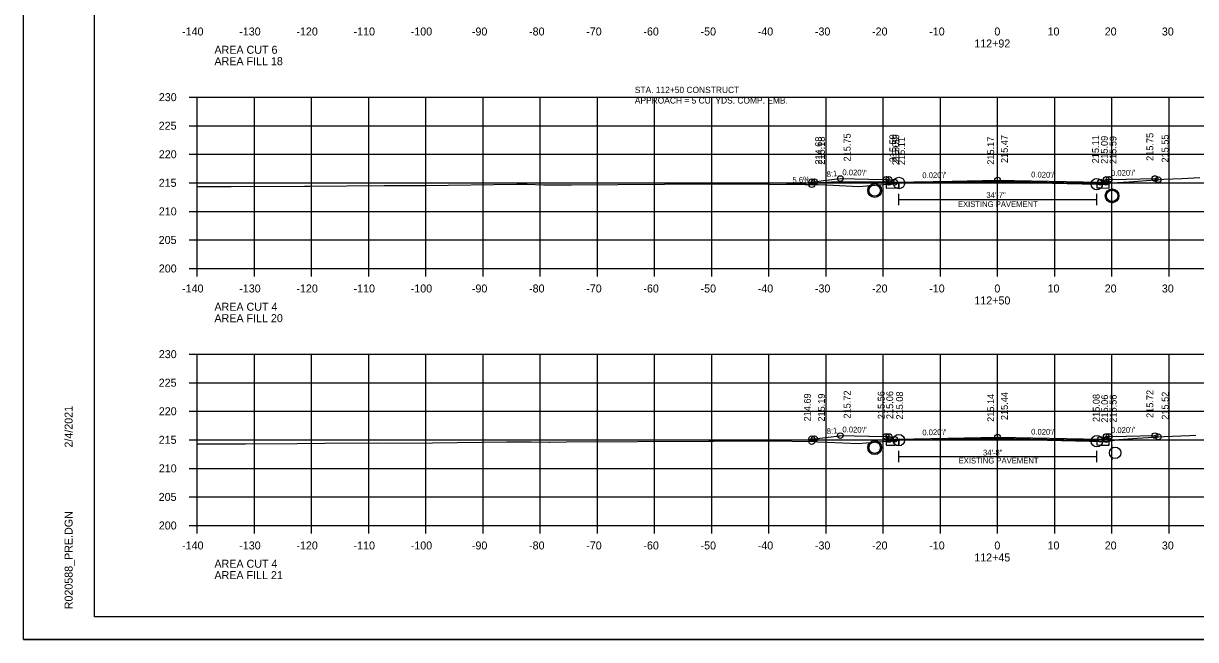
# Model space of a CAD drawing. Extents: x 1368968 to 1369915, y 377395 to 380381.
# Drawn here: x 1369581.4 to 1369786.4, y 377821.4 to 377929.3 of the extents above; entities that cross this region are included whole.
import ezdxf

# ---------------------------------------------------------------- set-up
doc = ezdxf.new("R2010")
doc.units = 0
for name, color, linetype in [('Default', 7, 'Continuous'), ('S_BORDER_NO_PLOT', 7, 'Continuous'), ('S_BREAKLINE_ANNOT', 7, 'Continuous'), ('S_BRIDGE', 7, 'Continuous'), ('S_BRIDGE_ANNOT', 7, 'Continuous'), ('S_CONTOUR_MINOR', 7, 'Continuous'), ('S_CROSS_DRAIN', 7, 'Continuous'), ('S_CTL_TABLE', 7, 'Continuous'), ('S_CURB_ANNOT', 7, 'Continuous'), ('S_DITCHLINE_ANNOT', 7, 'Continuous'), ('S_DROP_INLET', 7, 'Continuous'), ('S_EXIST_ROW_ANNOT', 7, 'Continuous'), ('S_EXISTING_ALIGNMENT_ANNOT', 7, 'Continuous'), ('S_FENCE', 7, 'Continuous')]:
    doc.layers.add(name, color=color, linetype=linetype)

msp = doc.modelspace()

# ---------------------------------------------------------------- linework, layer by layer
at = {"layer": 'Default'}
for p, q in [((1369734.53, 377901.31), (1369734.53, 377900.48)), ((1369734.5, 377856.28), (1369734.5, 377855.45))]:
    msp.add_line(p, q, dxfattribs=at)
at = {"layer": 'S_BORDER_NO_PLOT'}
for points in [[(1369732.27, 377901.94), (1369732.28, 377900.43), (1369733.78, 377900.46), (1369734.53, 377900.48), (1369734.53, 377901.31), (1369751.78, 377901.65), (1369769.13, 377901.31), (1369769.13, 377900.48), (1369769.78, 377900.46), (1369771.28, 377900.43), (1369771.29, 377901.94)], [(1369732.27, 377856.92), (1369732.28, 377855.41), (1369733.78, 377855.44), (1369734.5, 377855.45), (1369734.5, 377856.28), (1369751.78, 377856.63), (1369769.15, 377856.28), (1369769.15, 377855.45), (1369769.78, 377855.44), (1369771.28, 377855.41), (1369771.29, 377856.92)]]:
    msp.add_lwpolyline(points, dxfattribs=at)
at = {"layer": 'S_BREAKLINE_ANNOT'}
for p, q in [((1369610.38, 377916.35), (1369611.78, 377916.35)), ((1369611.78, 377886.35), (1369611.78, 377916.35)), ((1369610.38, 377911.35), (1369611.78, 377911.35)), ((1369610.38, 377906.35), (1369611.78, 377906.35)), ((1369610.38, 377901.35), (1369611.78, 377901.35)), ((1369610.38, 377896.35), (1369611.78, 377896.35)), ((1369610.38, 377891.35), (1369611.78, 377891.35)), ((1369610.38, 377886.35), (1369611.78, 377886.35)), ((1369611.78, 377886.35), (1369891.78, 377886.35)), ((1369611.78, 377884.95), (1369611.78, 377886.35)), ((1369621.78, 377884.95), (1369621.78, 377886.35)), ((1369631.78, 377884.95), (1369631.78, 377886.35)), ((1369641.78, 377884.95), (1369641.78, 377886.35)), ((1369651.78, 377884.95), (1369651.78, 377886.35)), ((1369661.78, 377884.95), (1369661.78, 377886.35)), ((1369671.78, 377884.95), (1369671.78, 377886.35)), ((1369681.78, 377884.95), (1369681.78, 377886.35)), ((1369691.78, 377884.95), (1369691.78, 377886.35)), ((1369701.78, 377884.95), (1369701.78, 377886.35)), ((1369711.78, 377884.95), (1369711.78, 377886.35)), ((1369721.78, 377884.95), (1369721.78, 377886.35)), ((1369731.78, 377884.95), (1369731.78, 377886.35)), ((1369741.78, 377884.95), (1369741.78, 377886.35)), ((1369751.78, 377884.95), (1369751.78, 377886.35)), ((1369761.78, 377884.95), (1369761.78, 377886.35)), ((1369771.78, 377884.95), (1369771.78, 377886.35)), ((1369781.78, 377884.95), (1369781.78, 377886.35)), ((1369610.38, 377871.35), (1369611.78, 377871.35)), ((1369611.78, 377841.35), (1369611.78, 377871.35)), ((1369610.38, 377866.35), (1369611.78, 377866.35)), ((1369610.38, 377861.35), (1369611.78, 377861.35)), ((1369610.38, 377856.35), (1369611.78, 377856.35)), ((1369610.38, 377851.35), (1369611.78, 377851.35)), ((1369610.38, 377846.35), (1369611.78, 377846.35)), ((1369610.38, 377841.35), (1369611.78, 377841.35)), ((1369611.78, 377841.35), (1369891.78, 377841.35)), ((1369611.78, 377839.95), (1369611.78, 377841.35)), ((1369621.78, 377839.95), (1369621.78, 377841.35)), ((1369631.78, 377839.95), (1369631.78, 377841.35)), ((1369641.78, 377839.95), (1369641.78, 377841.35)), ((1369651.78, 377839.95), (1369651.78, 377841.35)), ((1369661.78, 377839.95), (1369661.78, 377841.35)), ((1369671.78, 377839.95), (1369671.78, 377841.35)), ((1369681.78, 377839.95), (1369681.78, 377841.35)), ((1369691.78, 377839.95), (1369691.78, 377841.35)), ((1369701.78, 377839.95), (1369701.78, 377841.35)), ((1369711.78, 377839.95), (1369711.78, 377841.35)), ((1369721.78, 377839.95), (1369721.78, 377841.35)), ((1369731.78, 377839.95), (1369731.78, 377841.35)), ((1369741.78, 377839.95), (1369741.78, 377841.35)), ((1369751.78, 377839.95), (1369751.78, 377841.35)), ((1369761.78, 377839.95), (1369761.78, 377841.35)), ((1369771.78, 377839.95), (1369771.78, 377841.35)), ((1369781.78, 377839.95), (1369781.78, 377841.35))]:
    msp.add_line(p, q, dxfattribs=at)
at = {"layer": 'S_BRIDGE_ANNOT'}
for p, q in [((1369593.78, 377825.35), (1369593.78, 378030.81)), ((1369593.78, 377825.35), (1369593.78, 377825.35)), ((1369909.96, 377825.35), (1369593.78, 377825.35))]:
    msp.add_line(p, q, dxfattribs=at)
at = {"layer": 'S_CROSS_DRAIN'}
for p, q in [((1369714.84, 377901.1), (1369722.78, 377901.54)), ((1369732.78, 377901.44), (1369722.78, 377901.54)), ((1369734.53, 377898.45), (1369760.85, 377898.45)), ((1369734.53, 377898.45), (1369769.13, 377898.45)), ((1369734.5, 377853.41), (1369760.81, 377853.41)), ((1369734.5, 377853.41), (1369769.15, 377853.41))]:
    msp.add_line(p, q, dxfattribs=at)
at = {"layer": 'S_CTL_TABLE'}
for points in [[(1369611.78, 377900.68), (1369616.62, 377900.7), (1369617.72, 377900.7), (1369630.56, 377900.79), (1369631.46, 377900.79), (1369644.49, 377900.87), (1369650.58, 377900.87), (1369651.62, 377900.87), (1369667.69, 377901.11), (1369669.41, 377901.14), (1369669.48, 377901.14), (1369672.36, 377901.01), (1369677.25, 377901.01), (1369701.63, 377901.18), (1369703.02, 377901.19), (1369703.04, 377901.19), (1369703.07, 377901.19), (1369703.5, 377901.19), (1369711.89, 377901.13), (1369718.12, 377901.04), (1369720.39, 377901.03), (1369721.9, 377900.97), (1369727.5, 377900.71), (1369731.06, 377901.02), (1369734.53, 377901.32), (1369743.41, 377901.44), (1369750.71, 377901.55), (1369761.38, 377901.31), (1369769.13, 377901.13), (1369770.2, 377901.1), (1369771.72, 377901.32), (1369774.8, 377901.55), (1369780.84, 377901.97), (1369783.99, 377902.09), (1369787.17, 377902.29)], [(1369611.78, 377855.62), (1369615.1, 377855.63), (1369620.22, 377855.66), (1369629.24, 377855.71), (1369634.11, 377855.74), (1369643.35, 377855.8), (1369647.68, 377855.79), (1369652.94, 377855.81), (1369665.87, 377856), (1369670.19, 377856.02), (1369673.34, 377855.94), (1369673.47, 377855.96), (1369676.39, 377855.98), (1369701.28, 377856.14), (1369702.07, 377856.14), (1369702.92, 377856.18), (1369710.84, 377856.15), (1369711.88, 377856.16), (1369719.73, 377856.04), (1369720.25, 377856.02), (1369721.95, 377855.94), (1369727.44, 377855.68), (1369728.77, 377855.8), (1369734.5, 377856.28), (1369749.1, 377856.49), (1369750.69, 377856.52), (1369767.86, 377856.13), (1369769.15, 377856.1), (1369769.92, 377856.08), (1369770.77, 377856.06), (1369771.88, 377856.22), (1369772.97, 377856.39), (1369776.23, 377856.62), (1369780.87, 377856.94), (1369785.33, 377857.12), (1369786.45, 377857.19)]]:
    msp.add_lwpolyline(points, dxfattribs=at)
at = {"layer": 'S_CURB_ANNOT'}
for points in [[(1369719.27, 377901.03), (1369719.27, 377901.53), (1369719.77, 377901.53), (1369721.31, 377901.73), (1369724.27, 377902.1), (1369729.27, 377902), (1369732.27, 377901.94), (1369732.46, 377901.94), (1369732.77, 377901.94), (1369732.78, 377901.44), (1369733.78, 377901.46), (1369743.85, 377901.67), (1369751.77, 377901.82), (1369751.78, 377901.82), (1369769.78, 377901.46), (1369770.78, 377901.44), (1369770.79, 377901.94), (1369770.79, 377901.94), (1369771.29, 377901.94), (1369774.29, 377902), (1369774.29, 377902), (1369779.29, 377902.1), (1369779.63, 377901.99), (1369779.89, 377901.9)], [(1369719.27, 377856.04), (1369719.27, 377856.54), (1369719.77, 377856.54), (1369722.15, 377856.83), (1369724.21, 377857.07), (1369724.27, 377857.08), (1369729.23, 377856.98), (1369729.27, 377856.98), (1369729.29, 377856.98), (1369732.27, 377856.92), (1369732.27, 377856.92), (1369732.37, 377856.92), (1369732.77, 377856.92), (1369732.77, 377856.69), (1369732.78, 377856.42), (1369732.8, 377856.42), (1369733.78, 377856.44), (1369734.22, 377856.45), (1369751.78, 377856.8), (1369752.01, 377856.79), (1369769.78, 377856.44), (1369769.78, 377856.44), (1369770.78, 377856.42), (1369770.78, 377856.49), (1369770.79, 377856.92), (1369770.88, 377856.92), (1369771.29, 377856.92), (1369774.23, 377856.98), (1369774.29, 377856.98), (1369779.21, 377857.08), (1369779.29, 377857.08), (1369779.54, 377856.99), (1369779.9, 377856.87)]]:
    msp.add_lwpolyline(points, dxfattribs=at)
at = {"layer": 'S_DITCHLINE_ANNOT'}
for p, q in [((1369611.78, 377916.35), (1369891.78, 377916.35)), ((1369611.78, 377886.35), (1369611.78, 377916.35)), ((1369621.78, 377886.35), (1369621.78, 377916.35)), ((1369631.78, 377886.35), (1369631.78, 377916.35)), ((1369641.78, 377886.35), (1369641.78, 377916.35)), ((1369651.78, 377886.35), (1369651.78, 377916.35)), ((1369661.78, 377886.35), (1369661.78, 377916.35)), ((1369671.78, 377886.35), (1369671.78, 377916.35)), ((1369681.78, 377886.35), (1369681.78, 377916.35)), ((1369691.78, 377886.35), (1369691.78, 377916.35)), ((1369701.78, 377886.35), (1369701.78, 377916.35)), ((1369711.78, 377886.35), (1369711.78, 377916.35)), ((1369721.78, 377886.35), (1369721.78, 377916.35)), ((1369731.78, 377886.35), (1369731.78, 377916.35)), ((1369741.78, 377886.35), (1369741.78, 377916.35)), ((1369751.78, 377886.35), (1369751.78, 377916.35)), ((1369761.78, 377886.35), (1369761.78, 377916.35)), ((1369771.78, 377886.35), (1369771.78, 377916.35)), ((1369781.78, 377886.35), (1369781.78, 377916.35)), ((1369611.78, 377911.35), (1369891.78, 377911.35)), ((1369611.78, 377906.35), (1369891.78, 377906.35)), ((1369611.78, 377901.35), (1369891.78, 377901.35)), ((1369611.78, 377896.35), (1369891.78, 377896.35)), ((1369611.78, 377891.35), (1369891.78, 377891.35)), ((1369611.78, 377886.35), (1369891.78, 377886.35)), ((1369611.78, 377871.35), (1369891.78, 377871.35)), ((1369611.78, 377841.35), (1369611.78, 377871.35)), ((1369621.78, 377841.35), (1369621.78, 377871.35)), ((1369631.78, 377841.35), (1369631.78, 377871.35)), ((1369641.78, 377841.35), (1369641.78, 377871.35)), ((1369651.78, 377841.35), (1369651.78, 377871.35)), ((1369661.78, 377841.35), (1369661.78, 377871.35)), ((1369671.78, 377841.35), (1369671.78, 377871.35)), ((1369681.78, 377841.35), (1369681.78, 377871.35)), ((1369691.78, 377841.35), (1369691.78, 377871.35)), ((1369701.78, 377841.35), (1369701.78, 377871.35)), ((1369711.78, 377841.35), (1369711.78, 377871.35)), ((1369721.78, 377841.35), (1369721.78, 377871.35)), ((1369731.78, 377841.35), (1369731.78, 377871.35)), ((1369741.78, 377841.35), (1369741.78, 377871.35)), ((1369751.78, 377841.35), (1369751.78, 377871.35)), ((1369761.78, 377841.35), (1369761.78, 377871.35)), ((1369771.78, 377841.35), (1369771.78, 377871.35)), ((1369781.78, 377841.35), (1369781.78, 377871.35)), ((1369611.78, 377866.35), (1369891.78, 377866.35)), ((1369611.78, 377861.35), (1369891.78, 377861.35)), ((1369611.78, 377856.35), (1369891.78, 377856.35)), ((1369611.78, 377851.35), (1369891.78, 377851.35)), ((1369611.78, 377846.35), (1369891.78, 377846.35)), ((1369611.78, 377841.35), (1369891.78, 377841.35))]:
    msp.add_line(p, q, dxfattribs=at)
at = {"layer": 'S_DROP_INLET'}
for p, q in [((1369771.85, 377900.33), (1369771.8, 377900.26)), ((1369771.85, 377897.91), (1369771.8, 377897.84)), ((1369771.83, 377855.3), (1369771.8, 377855.26)), ((1369771.83, 377852.89), (1369771.8, 377852.84)), ((1369581.38, 377821.37), (1369914.71, 377821.37))]:
    msp.add_line(p, q, dxfattribs=at)
for points in [[(1369581.37, 378034.71), (1369914.71, 378034.71), (1369914.71, 377821.37), (1369581.37, 377821.37)], [(1369827.7, 378030.81), (1369827.7, 378020.93), (1369863.43, 378020.93), (1369863.43, 378018.01), (1369886.63, 378018.01), (1369886.63, 377993.68), (1369909.96, 377993.68), (1369909.96, 377825.35), (1369593.78, 377825.35), (1369593.78, 378030.81)]]:
    msp.add_lwpolyline(points, close=True, dxfattribs=at)
for centre, radius in [((1369719.27, 377901.53), 0.5), ((1369719.27, 377901.03), 0.5), ((1369719.77, 377901.53), 0.5), ((1369724.27, 377902.1), 0.5), ((1369730.28, 377900), 1.21), ((1369732.27, 377901.94), 0.5), ((1369732.77, 377901.94), 0.5), ((1369732.78, 377901.44), 0.5), ((1369733.78, 377901.46), 0.5), ((1369733.78, 377901.46), 0.5), ((1369734.53, 377901.32), 1), ((1369751.78, 377901.82), 0.5), ((1369769.13, 377901.13), 1), ((1369769.78, 377901.46), 0.5), ((1369769.78, 377901.46), 0.5), ((1369770.78, 377901.44), 0.5), ((1369770.79, 377901.94), 0.5), ((1369771.29, 377901.94), 0.5), ((1369779.29, 377902.1), 0.5), ((1369779.89, 377901.9), 0.5), ((1369771.81, 377899.07), 1.21), ((1369719.27, 377856.54), 0.5), ((1369719.27, 377856.04), 0.5), ((1369719.77, 377856.54), 0.5), ((1369724.27, 377857.08), 0.5), ((1369730.28, 377854.98), 1.21), ((1369732.27, 377856.92), 0.5), ((1369732.77, 377856.92), 0.5), ((1369732.78, 377856.42), 0.5), ((1369733.78, 377856.44), 0.5), ((1369733.78, 377856.44), 0.5), ((1369734.5, 377856.28), 1), ((1369751.78, 377856.8), 0.5), ((1369769.15, 377856.1), 1), ((1369769.78, 377856.44), 0.5), ((1369769.78, 377856.44), 0.5), ((1369770.78, 377856.42), 0.5), ((1369770.79, 377856.92), 0.5), ((1369771.29, 377856.92), 0.5), ((1369779.29, 377857.08), 0.5), ((1369779.9, 377856.87), 0.5)]:
    msp.add_circle(centre, radius, dxfattribs=at)
at = {"layer": 'S_EXIST_ROW_ANNOT'}
for p, q in [((1369734.53, 377897.45), (1369734.53, 377899.45)), ((1369734.53, 377897.45), (1369734.53, 377899.45)), ((1369769.13, 377897.45), (1369769.13, 377899.45)), ((1369771.85, 377900.12), (1369771.8, 377900.05)), ((1369771.89, 377900.24), (1369771.9, 377900.22)), ((1369771.89, 377900.03), (1369771.9, 377900.01)), ((1369771.85, 377898.12), (1369771.8, 377898.05)), ((1369771.89, 377898.03), (1369771.9, 377898.01)), ((1369771.89, 377897.82), (1369771.9, 377897.8)), ((1369734.5, 377852.41), (1369734.5, 377854.41)), ((1369734.5, 377852.41), (1369734.5, 377854.41)), ((1369769.15, 377852.41), (1369769.15, 377854.41)), ((1369771.83, 377855.09), (1369771.8, 377855.05)), ((1369771.83, 377853.09), (1369771.8, 377853.05))]:
    msp.add_line(p, q, dxfattribs=at)
for centre in [(1369730.28, 377900), (1369771.81, 377899.07), (1369730.28, 377854.98), (1369772.36, 377854.07)]:
    msp.add_circle(centre, 1, dxfattribs=at)
at = {"layer": 'S_EXISTING_ALIGNMENT_ANNOT'}
for p, q in [((1369751.78, 377901.52), (1369751.78, 377911.52)), ((1369751.78, 377856.49), (1369751.78, 377866.49))]:
    msp.add_line(p, q, dxfattribs=at)

# ---------------------------------------------------------------- texts
at = {"layer": 'S_BRIDGE'}
for s, p in [('-140', (1369609.12, 377927.15)), ('-130', (1369619.12, 377927.15)), ('-120', (1369629.12, 377927.15)), ('-110', (1369639.12, 377927.15)), ('-100', (1369649.12, 377927.15)), ('-90', (1369659.82, 377927.15)), ('-80', (1369669.82, 377927.15)), ('-70', (1369679.82, 377927.15)), ('-60', (1369689.82, 377927.15)), ('-50', (1369699.82, 377927.15)), ('-40', (1369709.82, 377927.15)), ('-30', (1369719.82, 377927.15)), ('-20', (1369729.82, 377927.15)), ('-10', (1369739.82, 377927.15)), ('0', (1369751.22, 377927.15)), ('10', (1369760.52, 377927.15)), ('20', (1369770.52, 377927.15)), ('30', (1369780.52, 377927.15)), ('AREA CUT 6', (1369614.78, 377923.95)), ('112+92', (1369747.7, 377925.05)), ('AREA FILL 18', (1369614.78, 377921.95)), ('230', (1369605.05, 377915.65)), ('225', (1369605.03, 377910.65)), ('220', (1369605.05, 377905.65)), ('215', (1369605.03, 377900.65)), ('210', (1369605.05, 377895.65)), ('205', (1369605.03, 377890.65)), ('200', (1369605.05, 377885.65)), ('-140', (1369609.12, 377882.15)), ('-130', (1369619.12, 377882.15)), ('-120', (1369629.12, 377882.15)), ('-110', (1369639.12, 377882.15)), ('-100', (1369649.12, 377882.15)), ('-90', (1369659.82, 377882.15)), ('-80', (1369669.82, 377882.15)), ('-70', (1369679.82, 377882.15)), ('-60', (1369689.82, 377882.15)), ('-50', (1369699.82, 377882.15)), ('-40', (1369709.82, 377882.15)), ('-30', (1369719.82, 377882.15)), ('-20', (1369729.82, 377882.15)), ('-10', (1369739.82, 377882.15)), ('0', (1369751.22, 377882.15)), ('10', (1369760.52, 377882.15)), ('20', (1369770.52, 377882.15)), ('30', (1369780.52, 377882.15)), ('AREA CUT 4', (1369614.78, 377878.95)), ('112+50', (1369747.72, 377880.05)), ('AREA FILL 20', (1369614.78, 377876.95)), ('230', (1369605.05, 377870.65)), ('225', (1369605.03, 377865.65)), ('220', (1369605.05, 377860.65)), ('215', (1369605.03, 377855.65)), ('210', (1369605.05, 377850.65)), ('205', (1369605.03, 377845.65)), ('200', (1369605.05, 377840.65)), ('-140', (1369609.12, 377837.15)), ('-130', (1369619.12, 377837.15)), ('-120', (1369629.12, 377837.15)), ('-110', (1369639.12, 377837.15)), ('-100', (1369649.12, 377837.15)), ('-90', (1369659.82, 377837.15)), ('-80', (1369669.82, 377837.15)), ('-70', (1369679.82, 377837.15)), ('-60', (1369689.82, 377837.15)), ('-50', (1369699.82, 377837.15)), ('-40', (1369709.82, 377837.15)), ('-30', (1369719.82, 377837.15)), ('-20', (1369729.82, 377837.15)), ('-10', (1369739.82, 377837.15)), ('0', (1369751.22, 377837.15)), ('10', (1369760.52, 377837.15)), ('20', (1369770.52, 377837.15)), ('30', (1369780.52, 377837.15)), ('AREA CUT 4', (1369614.78, 377833.95)), ('112+45', (1369747.7, 377835.05)), ('AREA FILL 21', (1369614.78, 377831.95))]:
    msp.add_text(s, height=1.4, dxfattribs=at).set_placement(p)
at = {"layer": 'S_BRIDGE_ANNOT'}
for s, p in [('2/4/2021', (1369589.97, 377855)), ('R020588_PRE.DGN', (1369589.97, 377826.68))]:
    msp.add_text(s, height=1.4, rotation=90, dxfattribs=at).set_placement(p)
at = {"layer": 'S_CONTOUR_MINOR'}
for s, p in [('STA. 112+50 CONSTRUCT ', (1369688.32, 377917.07)), ('APPROACH = 5 CU. YDS. COMP. EMB.', (1369688.32, 377915.23))]:
    msp.add_text(s, height=1.1, dxfattribs=at).set_placement(p)
at = {"layer": 'S_CROSS_DRAIN'}
msp.add_text('5.6%', height=1, rotation=3.2052, dxfattribs=at).set_placement((1369715.93, 377901.31))
at = {"layer": 'S_EXIST_ROW_ANNOT'}
for s, p in [('34\'-7"', (1369749.81, 377898.71)), ('EXISTING PAVEMENT', (1369744.84, 377897.12)), ('34\'-8"', (1369749.23, 377853.61)), ('EXISTING PAVEMENT', (1369744.97, 377852.21))]:
    msp.add_text(s, height=1, dxfattribs=at).set_placement(p)
at = {"layer": 'S_EXISTING_ALIGNMENT_ANNOT'}
for s, p in [('214.68', (1369721.07, 377904.53)), ('215.18', (1369721.57, 377904.53)), ('215.75', (1369726.07, 377905.1)), ('215.59', (1369734.07, 377904.94)), ('215.59', (1369734.57, 377904.94)), ('215.09', (1369734.58, 377904.44)), ('215.11', (1369735.58, 377904.46)), ('215.17', (1369751.18, 377904.52)), ('215.47', (1369753.58, 377904.82)), ('215.11', (1369769.52, 377904.77)), ('215.09', (1369771.06, 377904.68)), ('215.59', (1369772.58, 377904.64)), ('215.75', (1369779.02, 377905.19)), ('215.55', (1369781.69, 377904.9)), ('214.69', (1369719.11, 377859.57)), ('215.19', (1369721.57, 377859.54)), ('215.72', (1369726.07, 377860.08)), ('215.56', (1369732.02, 377859.97)), ('215.06', (1369733.52, 377859.98)), ('215.08', (1369735.24, 377859.9)), ('215.14', (1369751.18, 377859.49)), ('215.44', (1369753.58, 377859.8)), ('215.08', (1369769.64, 377859.47)), ('215.06', (1369771.11, 377859.35)), ('215.56', (1369772.6, 377859.36)), ('215.72', (1369779.02, 377860.18)), ('215.52', (1369781.7, 377859.87))]:
    msp.add_text(s, height=1.2, rotation=90, dxfattribs=at).set_placement(p)
at = {"layer": 'S_FENCE'}
for s, rotation, p in [('8:1', 7.2311, (1369721.95, 377902.31)), ("0.020'/'", 358.8542, (1369724.63, 377902.7)), ("0.020'/'", 1.1457, (1369738.62, 377902.16)), ("0.020'/'", 358.8543, (1369757.64, 377902.31)), ("0.020'/'", 1.1458, (1369771.63, 377902.55)), ('8:1', 6.7434, (1369721.96, 377857.31)), ("0.020'/'", 358.8543, (1369724.63, 377857.67)), ("0.020'/'", 1.1458, (1369738.62, 377857.13)), ("0.020'/'", 358.8542, (1369757.64, 377857.28)), ("0.020'/'", 1.1458, (1369771.63, 377857.52))]:
    msp.add_text(s, height=1, rotation=rotation, dxfattribs=at).set_placement(p)

doc.saveas('drawing.dxf')
